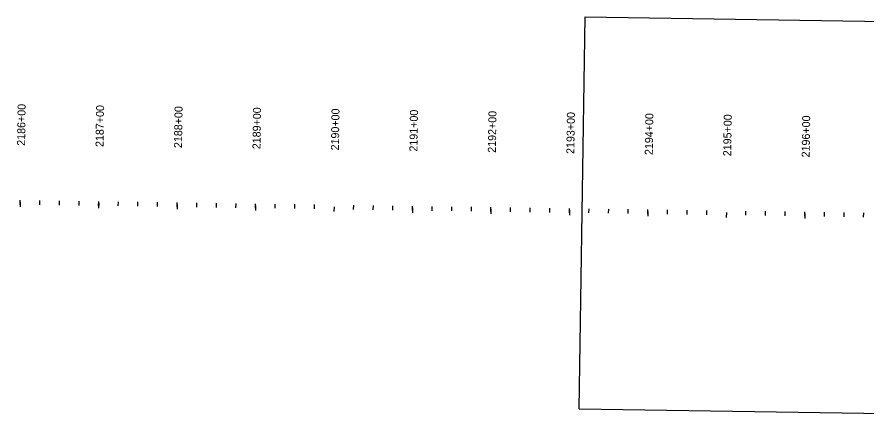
# Model space of a CAD drawing. Extents: x 14295116 to 14303545, y 8637313 to 8653417.
# Drawn here: x 14299107 to 14300189, y 8637313 to 8637836 of the extents above; entities that cross this region are included whole.
import ezdxf

# ---------------------------------------------------------------- set-up
doc = ezdxf.new("R2010")
doc.units = 0
for name, color, linetype in [('_CIVIL_CONSTRUCTION', 7, 'Continuous'), ('Draft_DNC', 7, 'Continuous'), ('G Prop 6 Valve (B1) CELL', 7, 'Continuous')]:
    doc.layers.add(name, color=color, linetype=linetype)

msp = doc.modelspace()

# ---------------------------------------------------------------- linework, layer by layer
at = {"layer": '_CIVIL_CONSTRUCTION'}
for p, q in [((14299823.4, 8637336.3), (14299830.8, 8637836.3)), ((14299830.8, 8637836.3), (14301398.1, 8637813)), ((14299823.4, 8637336.3), (14301390.7, 8637313))]:
    msp.add_line(p, q, dxfattribs=at)
at = {"layer": 'Draft_DNC'}
for p, q in [((14299111, 8637600), (14299110.9, 8637593.9)), ((14299135.9, 8637596.5), (14299136, 8637602)), ((14299160.9, 8637596.2), (14299161, 8637601.6)), ((14299185.9, 8637595.8), (14299186, 8637601.3)), ((14299235.9, 8637595.1), (14299236, 8637600.5)), ((14299260.9, 8637594.7), (14299261, 8637600.2)), ((14299211, 8637598.5), (14299210.9, 8637592.4)), ((14299285.9, 8637594.3), (14299286, 8637599.8)), ((14299311, 8637597), (14299310.9, 8637590.9)), ((14299335.9, 8637593.6), (14299336, 8637599)), ((14299360.9, 8637593.2), (14299361, 8637598.7)), ((14299385.9, 8637592.8), (14299386, 8637598.3)), ((14299410.9, 8637595.5), (14299410.9, 8637589.4)), ((14299435.9, 8637592.1), (14299436, 8637597.6)), ((14299460.9, 8637591.7), (14299461, 8637597.2)), ((14299485.9, 8637591.4), (14299486, 8637596.8)), ((14299510.9, 8637594), (14299510.8, 8637587.9)), ((14299535.9, 8637590.6), (14299536, 8637596.1)), ((14299560.9, 8637590.2), (14299561, 8637595.7)), ((14299585.9, 8637589.9), (14299586, 8637595.3)), ((14299610.9, 8637592.6), (14299610.8, 8637586.4)), ((14299635.9, 8637589.1), (14299636, 8637594.6)), ((14299660.9, 8637588.8), (14299661, 8637594.2)), ((14299685.9, 8637588.4), (14299685.9, 8637593.8)), ((14299710.9, 8637591.1), (14299710.8, 8637584.9)), ((14299735.9, 8637587.6), (14299735.9, 8637593.1)), ((14299760.9, 8637587.3), (14299760.9, 8637592.7)), ((14299785.9, 8637586.9), (14299785.9, 8637592.4)), ((14299810.9, 8637589.6), (14299810.8, 8637583.5)), ((14299835.8, 8637586.2), (14299835.9, 8637591.6)), ((14299860.8, 8637585.8), (14299860.9, 8637591.2)), ((14299885.8, 8637585.4), (14299885.9, 8637590.9)), ((14299935.8, 8637584.7), (14299935.9, 8637590.1)), ((14299960.8, 8637584.3), (14299960.9, 8637589.8)), ((14299985.8, 8637583.9), (14299985.9, 8637589.4)), ((14299910.9, 8637588.1), (14299910.8, 8637582)), ((14300010.9, 8637586.6), (14300010.8, 8637580.5)), ((14300035.8, 8637583.2), (14300035.9, 8637588.6)), ((14300060.8, 8637582.8), (14300060.9, 8637588.3)), ((14300085.8, 8637582.4), (14300085.9, 8637587.9)), ((14300110.9, 8637585.1), (14300110.8, 8637579)), ((14300135.8, 8637581.7), (14300135.9, 8637587.2)), ((14300160.8, 8637581.3), (14300160.9, 8637586.8)), ((14300185.8, 8637581), (14300185.9, 8637586.4))]:
    msp.add_line(p, q, dxfattribs=at)
at = {"layer": 'G Prop 6 Valve (B1) CELL'}
for p, q in [((14299110.9, 8637596.9), (14299111, 8637602.4)), ((14299210.9, 8637595.4), (14299211, 8637600.9)), ((14299310.9, 8637593.9), (14299311, 8637599.4)), ((14299410.9, 8637592.5), (14299411, 8637597.9)), ((14299510.9, 8637594), (14299510.8, 8637587.9)), ((14299610.9, 8637589.5), (14299611, 8637595)), ((14299710.9, 8637588), (14299710.9, 8637593.5)), ((14299810.9, 8637586.5), (14299810.9, 8637592)), ((14299910.8, 8637585), (14299910.9, 8637590.5)), ((14300010.9, 8637586.6), (14300010.8, 8637580.5)), ((14300110.8, 8637582.1), (14300110.9, 8637587.5))]:
    msp.add_line(p, q, dxfattribs=at)

# ---------------------------------------------------------------- texts
at = {"layer": 'Draft_DNC'}
for s, p in [('2186+00', (14299117.1, 8637671.8)), ('2187+00', (14299217.1, 8637670.3)), ('2188+00', (14299317.1, 8637668.9)), ('2189+00', (14299417.1, 8637667.4)), ('2190+00', (14299517.1, 8637665.9)), ('2191+00', (14299617.1, 8637664.4)), ('2192+00', (14299717.1, 8637662.9)), ('2193+00', (14299817.1, 8637661.4)), ('2194+00', (14299917.1, 8637660)), ('2195+00', (14300017, 8637658.5)), ('2196+00', (14300117, 8637657))]:
    msp.add_text(s, height=10.2, rotation=89.1493, dxfattribs=at).set_placement(p)
at = {"layer": 'G Prop 6 Valve (B1) CELL'}
for s, p in [('2190+00', (14299517.1, 8637665.9)), ('2195+00', (14300017, 8637658.5))]:
    msp.add_text(s, height=10.2, rotation=89.1493, dxfattribs=at).set_placement(p)

doc.saveas('drawing.dxf')
